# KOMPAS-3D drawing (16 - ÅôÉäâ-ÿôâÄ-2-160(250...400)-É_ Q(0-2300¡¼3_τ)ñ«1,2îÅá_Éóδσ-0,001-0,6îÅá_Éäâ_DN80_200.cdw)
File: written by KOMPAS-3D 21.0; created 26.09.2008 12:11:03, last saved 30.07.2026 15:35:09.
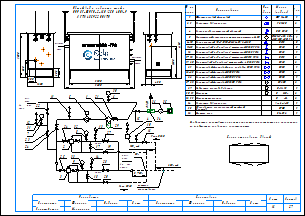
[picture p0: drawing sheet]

Sheets 1-2: A3, landscape

Document properties: Наименование: Макро:21; Автор: RaskoAdmin; Форматы листов документа: 2xA3; Полное имя файла: \\ur38nt01\Departments\КТО\КБ ПУРДГ\Заявки\Прайс-лист на типовые шкафы ГРПШ\ПУРДГ_стандарт_30_04_2026\ПУРДГ с РДГ(Н, В)\ПУРДГ-ШУГО-2-160(250...400)-Р_ Q(0-2300нм3_ч)до1,2МПа_Рвых-0,001-0,6МПа_РДГ_DN80_200.cdw

Title block, sheet 1: Наименование: Пункт учета газа / ПУГ-Ш-400-Р / ЛГТИ.485922.001ТУ; designation: ЛГТИ.03.4411141; sheet number: 1; Количество листов документа: 2; organisation: ООО "ЭЛЬСТЕР Газэлектроника"; Форматы листов документа: A3; stored path: C:\Рабочие документы\Компас\ПУГ\Схема.cdw; Разработал: Устинов; Проверил: Кошкин; Утвердил: Кошкин
Title block, sheet 2: sheet number: 2; stored path: D:\Рабочие документы\Заявки\ПУРДГ\ПУРДГ-ШУЭО-2-100-Р 4411220.cdw; designation, second copy: ЛГТИ.03.4411141-

Views: Вид 1, Вид 2
Referenced files: wcvoit.frw
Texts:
  Normal
  № на
  схеме
  Усл.
  обозн.
  Марка
  (модель)
  Кол.
  Фильтр газовый фланцевый
  ФГ 16-50
  Регулятор давления газа
  РДГ-50
  Клапан предохранительный сбросной
  ПСК DN25
  Измерительный комплекс с ротационным счетчиком Ду50
  СГ-ЭК-Р-(0,2...2,0)-
  Кран кнопочный VE-РАСКО-НЗ-1,6-G1/2-М20
  DN15
  Кран шаровой "под приварку" штуцерный DN20 PN16
  Кран шаровой "под приварку" штуцерный DN25 PN16
  DN20
  DN25
  Кран шаровой "под приварку" штуцерный DN15 PN16
  Кран шаровой "под приварку" штуцерный п/п DN20 PN16
  Кран шаровой фланцевый с мех. приводом DN50 PN16
  Кран шаровой фланцевый DN50 PN16
  Кран шаровой фланцевый DN80 PN16
  Кран шаровой фланцевый DN200 PN16
  DN50
  DN80
  DN200
  Индикатор перепада давления
  Манометр
  Манометр-напоромер
  Обогреватель газогорелочный шкафной
  (Эльтон")
  Счетчик газа
  Delta 15
  0...     МПа
  0...     кПа
  Venio-A-15
  ОГШН
  BK-G1,6
  Выход газа
  Вход газа
  logo-rasko-ge.png
  DN 1
  местное
  сопротивление
  Римп DN20
  Выход
  газа
  Р=     кПа
  Вход
  Р=       МПа
  PDI
  Схема открывания дверей
  Предприятие изготовитель может заменять комплектующие на аналогичные,
  не ухудшающие заявленных характеристик.
  Общий вид и габариты шкафа
  ПУРДГ-ШУГО-2-160(250...400)-Р
  Должность
  Конструктор
  Фамилия
  Подпись
  Дата
  Согласовано
  Максимкин
  Лист
  Листов
  POLYLINE_STYLE_0.18_RGB_0_0_0
  POLYLINE_STYLE_0.50_RGB_0_0_0
  POLYLINE_STYLE_0.34_RGB_0_0_0
  PHANTOM_RGB_0_0_0_SC_1_THICK_0.18
  K5LT_THIN_RGB_0_0_0_THICK_0.18
  K5LT32769_RGB_0_0_0_THICK_0.18
  K5LT12_RGB_0_0_0_SC_1_THICK_0.18
  K5LT_DASHED_RGB_0_0_0_SC_1_THICK_0.18
  ACISOTGL_RGB_0_0_0_SC_0.8_THICK_0.25
  CONTINUOUS_RGB_0_127_31_THICK_0.3
  CONTINUOUS_RGB_0_0_255_THICK_0.35
  CONTINUOUS_RGB_255_0_0_THICK_0.35
  POLYLINE_STYLE_0.25_RGB_0_0_0
  CONTINUOUS_RGB_0_0_0_THICK_0.5
  POLYLINE_STYLE_0.35_RGB_0_0_255
  CONTINUOUS_RGB_0_0_0_THICK_0.4
  CONTINUOUS_RGB_0_0_0_THICK_0.35
  НЕВИДИМАЯ_RGB_0_0_0_SC_0.3_THICK_0.25
  СONTINUOUS_RGB_0_0_0_THICK_0.25
  ОСЕВАЯ2_RGB_248_153_30_SC_0.3_THICK_0.25
  Без оформления
Dimensions and other numbers on the sheet: 1; 2, 3; 2; 4; 5; -160 (250; 400)/1,6; 6-10; 11-15; 16; 17, 18; 19, 20; 21; 22-25; 26; 27, 28; 29; 30, 31; 32, 33; 34; 35; 36; 1500; 450; 500; 1200; 550; 305; 3300; 4130; 2000; 3600; 5,,,7DN 1; 7; 31; 12; 22; 23; 24; 11; 6; 30; 32; 8; 13; 27; 19; 10; 25; 33; 9; 3; 14; 28; 20; 17; 18; 15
